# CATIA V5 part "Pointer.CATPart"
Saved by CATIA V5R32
Part number: Part1
Bounding box of the stored display mesh (mm): x -12.875 to 12.875, y -12.732 to 12.732, z 0 to 100
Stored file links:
  D:\PROJECTS\Project 2022\CATIA V5 6R 2022\Resources\Part Files\c16_catia_v5_6r2022_prt\Point Curve Joint-(16-36)\Pointer.CATPart
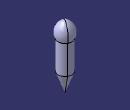
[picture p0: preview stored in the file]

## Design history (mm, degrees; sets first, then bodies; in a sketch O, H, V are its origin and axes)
Body1 (main body)
  Sketch1 on yz-plane, origin (0, 0, 0), H (0, 1, 0), V (0, 0, 1)
    line L1 (0, 0) -> (10.9446, 30.0702)
    point P1 (10.9446, 30.0702)
    line L2 (10.9446, 30.0702) -> (10.9446, 75.0702)
    point P2 (10.9446, 30.0702)
    point P3 (10.9446, 75.0702)
    arc A1 centre (-4.3336, 83.2301) radius 17.3208 from (10.9446, 75.0702) to (0, 100) ccw
    point P5 (0, 100)
    point P6 (10.9446, 91.3901)
    line L3 (0, 0) -> (0, 100)
    reference intersected line E1 through (0, 0) direction (-1, 0) from xy-plane
    reference intersected line E3 through (0, 0) direction (0, 1) from zx-plane
    radius A1 = 17.3208
    angle L1 L3 = 20
    distance O P1 = 32
    distance O P5 = 100
    distance P2 P3 = 45
    coincidence: P2 L1, P5 V, A1 P6, P6 L2, P2 P1, E3 P5, P1 L2
    vertical: L2 V, L3 V, E3 V
    horizontal: E1 H
    perpendicularity: E1 L2
  Shaft1: profile Sketch1, axis Sketch1.L3, angle 360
